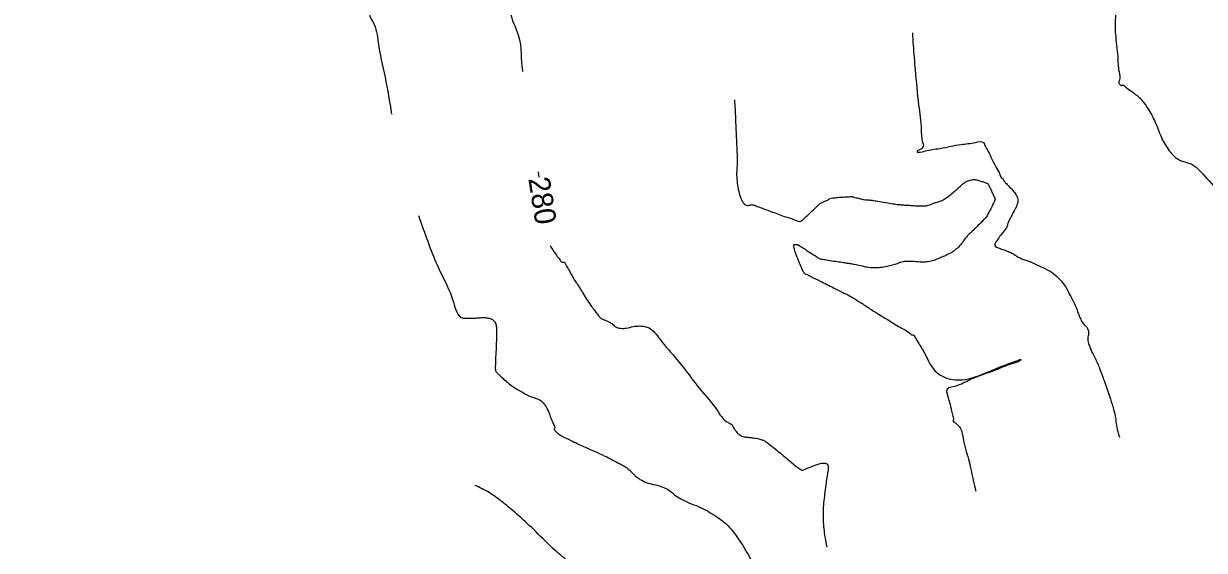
# Model space of a CAD drawing. Extents: x -478102 to -473059, y -1117705 to -1114104.
# Drawn here: x -476292.3 to -476071.3, y -1115340.6 to -1115242.1 of the extents above; entities that cross this region are included whole.
import ezdxf

# ---------------------------------------------------------------- set-up
doc = ezdxf.new("R2010")
doc.units = 0
for name, color, linetype in [('Vrstevnice_hlavni', 7, 'Continuous'), ('Vrstevnice_popis', 7, 'Continuous'), ('Vrstevnice_vedlejsi', 7, 'Continuous')]:
    doc.layers.add(name, color=color, linetype=linetype)

msp = doc.modelspace()

# ---------------------------------------------------------------- linework, layer by layer
at = {"layer": 'Vrstevnice_hlavni'}
msp.add_line((-476196.015, -1115269.846), (-476195.861, -1115270.85), dxfattribs=at)
for points in [[(-476040.384, -1115118.458), (-476041.47, -1115119.89), (-476042.412, -1115121.448), (-476043.751, -1115123.849), (-476045.488, -1115127.091), (-476046.696, -1115129.513), (-476047.375, -1115131.113), (-476047.526, -1115131.894), (-476048.073, -1115133.254), (-476049.018, -1115135.194), (-476050.36, -1115137.713), (-476052.374, -1115140.598), (-476055.061, -1115143.847), (-476058.422, -1115147.462), (-476060.881, -1115150.366), (-476062.441, -1115152.562), (-476063.1, -1115154.048), (-476064.028, -1115155.224), (-476065.225, -1115156.09), (-476066.691, -1115156.645), (-476068.203, -1115157.501), (-476069.761, -1115158.657), (-476071.364, -1115160.113), (-476073.585, -1115161.644), (-476076.424, -1115163.251), (-476079.881, -1115164.932), (-476082.243, -1115166.084), (-476083.511, -1115166.709), (-476083.684, -1115166.806), (-476083.884, -1115166.906), (-476084.109, -1115167.009), (-476084.361, -1115167.115), (-476085.47, -1115168.111), (-476087.436, -1115169.998), (-476090.259, -1115172.776), (-476094.056, -1115175.649), (-476098.828, -1115178.618), (-476104.575, -1115181.683), (-476109.757, -1115183.949), (-476114.374, -1115185.417), (-476118.425, -1115186.088), (-476122.042, -1115187.328), (-476125.226, -1115189.137), (-476127.977, -1115191.516), (-476131.019, -1115193.792), (-476134.353, -1115195.963), (-476137.979, -1115198.031), (-476141.984, -1115199.581), (-476146.368, -1115200.612), (-476151.132, -1115201.124), (-476157.864, -1115204.368), (-476166.565, -1115210.343), (-476177.234, -1115219.049), (-476184.652, -1115224.996), (-476188.817, -1115228.184), (-476189.731, -1115228.613), (-476190.168, -1115228.886), (-476190.128, -1115229.002), (-476189.61, -1115228.963), (-476189.269, -1115228.999), (-476189.104, -1115229.11), (-476189.116, -1115229.298), (-476189.143, -1115229.675), (-476189.187, -1115230.241), (-476189.246, -1115230.996), (-476189.162, -1115231.612), (-476188.933, -1115232.089), (-476188.56, -1115232.427), (-476188.448, -1115232.74), (-476188.595, -1115233.026), (-476189.004, -1115233.287), (-476189.464, -1115233.625), (-476189.976, -1115234.04), (-476190.541, -1115234.531), (-476191.953, -1115235.382), (-476194.211, -1115236.59), (-476197.317, -1115238.157), (-476199.41, -1115239.209), (-476200.49, -1115239.748), (-476200.557, -1115239.773), (-476200.072, -1115243.239), (-476199.036, -1115250.148), (-476198.895, -1115251.068)], [(-476193.757, -1115283.639), (-476192.399, -1115285.697), (-476191.876, -1115286.389), (-476191.509, -1115286.744), (-476191.298, -1115286.761), (-476191.153, -1115286.774), (-476191.075, -1115286.783), (-476191.063, -1115286.789), (-476190.853, -1115287.151), (-476190.446, -1115287.871), (-476189.842, -1115288.948), (-476188.923, -1115290.467), (-476187.688, -1115292.429), (-476186.137, -1115294.833), (-476184.891, -1115296.504), (-476183.948, -1115297.443), (-476183.309, -1115297.648), (-476182.68, -1115297.954), (-476182.06, -1115298.362), (-476181.45, -1115298.872), (-476180.595, -1115299.114), (-476179.497, -1115299.088), (-476178.155, -1115298.795), (-476176.997, -1115298.69), (-476176.025, -1115298.773), (-476175.238, -1115299.045), (-476173.224, -1115301.122), (-476169.984, -1115305.003), (-476165.518, -1115310.689), (-476162.449, -1115314.535), (-476160.779, -1115316.54), (-476160.507, -1115316.704), (-476160.264, -1115316.845), (-476160.048, -1115316.962), (-476159.86, -1115317.056), (-476159.707, -1115317.19), (-476159.59, -1115317.365), (-476159.508, -1115317.58), (-476159.311, -1115317.896), (-476158.998, -1115318.315), (-476158.57, -1115318.834), (-476158.007, -1115319.207), (-476157.308, -1115319.433), (-476156.473, -1115319.513), (-476155.76, -1115319.601), (-476155.169, -1115319.698), (-476154.699, -1115319.804), (-476154.303, -1115319.906), (-476153.978, -1115320.004), (-476153.727, -1115320.098), (-476153.145, -1115320.495), (-476152.232, -1115321.193), (-476150.988, -1115322.193), (-476149.831, -1115323.145), (-476148.761, -1115324.046), (-476147.778, -1115324.899), (-476147.017, -1115325.426), (-476146.478, -1115325.629), (-476146.16, -1115325.507), (-476145.635, -1115325.303), (-476144.904, -1115325.017), (-476143.967, -1115324.649), (-476143.233, -1115324.414), (-476142.702, -1115324.312), (-476142.375, -1115324.342), (-476142.123, -1115324.398), (-476141.945, -1115324.481), (-476141.842, -1115324.59), (-476141.767, -1115324.715), (-476141.722, -1115324.858), (-476141.705, -1115325.018), (-476141.842, -1115326.221), (-476142.131, -1115328.466), (-476142.574, -1115331.753), (-476142.636, -1115334.999), (-476142.32, -1115338.203), (-476141.962, -1115339.984)]]:
    msp.add_spline(points, degree=3, dxfattribs=at)
at = {"layer": 'Vrstevnice_vedlejsi'}
for points in [[(-476075.436, -1115157.873), (-476077.562, -1115158.907), (-476079.639, -1115159.964), (-476081.666, -1115161.045), (-476083.644, -1115162.149), (-476085.921, -1115163.289), (-476088.498, -1115164.465), (-476091.373, -1115165.676), (-476093.656, -1115166.843), (-476095.346, -1115167.967), (-476096.444, -1115169.047), (-476097.921, -1115170.165), (-476099.777, -1115171.319), (-476102.012, -1115172.511), (-476105.743, -1115173.677), (-476110.97, -1115174.816), (-476117.692, -1115175.928), (-476122.561, -1115177.005), (-476125.576, -1115178.045), (-476126.738, -1115179.05), (-476129.738, -1115180.989), (-476134.578, -1115183.864), (-476141.257, -1115187.673), (-476147.035, -1115190.356), (-476151.912, -1115191.911), (-476155.888, -1115192.338), (-476158.789, -1115192.754), (-476160.614, -1115193.159), (-476161.364, -1115193.552), (-476162.517, -1115193.939), (-476164.073, -1115194.319), (-476166.032, -1115194.693), (-476167.609, -1115195.158), (-476168.804, -1115195.715), (-476169.616, -1115196.364), (-476170.816, -1115197.116), (-476172.405, -1115197.973), (-476174.383, -1115198.934), (-476179.537, -1115202.555), (-476187.868, -1115208.836), (-476199.377, -1115217.776), (-476207.75, -1115223.932), (-476212.989, -1115227.302), (-476215.093, -1115227.888), (-476217.31, -1115229.046), (-476219.639, -1115230.776), (-476222.081, -1115233.079), (-476224.102, -1115235.091), (-476225.704, -1115236.812), (-476226.884, -1115238.243), (-476227.475, -1115239.561), (-476227.475, -1115240.767), (-476226.885, -1115241.861), (-476225.939, -1115245.662), (-476224.639, -1115252.17), (-476223.41, -1115259.087)], [(-476290.943, -1115168.232), (-476292.036, -1115168.129), (-476293.289, -1115168.17), (-476294.704, -1115168.355), (-476296.28, -1115168.684), (-476298.044, -1115169.506), (-476299.998, -1115170.82), (-476302.142, -1115172.626), (-476303.749, -1115173.838), (-476304.822, -1115174.454), (-476305.36, -1115174.476), (-476306.141, -1115174.653), (-476307.165, -1115174.987), (-476308.432, -1115175.476), (-476310.431, -1115176.469), (-476313.163, -1115177.965), (-476316.627, -1115179.965), (-476319.342, -1115180.948), (-476321.309, -1115180.916), (-476322.528, -1115179.868), (-476324.355, -1115178.896), (-476326.789, -1115178.002), (-476329.831, -1115177.184), (-476332.146, -1115176.734), (-476333.735, -1115176.651), (-476334.597, -1115176.934), (-476335.575, -1115177.335), (-476336.67, -1115177.853), (-476337.881, -1115178.489), (-476340.138, -1115179.828), (-476343.441, -1115181.87), (-476347.791, -1115184.616), (-476351.193, -1115186.546), (-476353.648, -1115187.661), (-476355.156, -1115187.959), (-476356.569, -1115188.49), (-476357.888, -1115189.253), (-476359.112, -1115190.247), (-476360.257, -1115191.198), (-476361.323, -1115192.106), (-476362.309, -1115192.972), (-476363.814, -1115193.968), (-476365.837, -1115195.095), (-476368.378, -1115196.353), (-476371.783, -1115197.918), (-476376.05, -1115199.79), (-476381.181, -1115201.968), (-476385.269, -1115204.296), (-476388.314, -1115206.773), (-476390.316, -1115209.399), (-476391.767, -1115211.232), (-476392.667, -1115212.272), (-476393.014, -1115212.519), (-476394.789, -1115214.333), (-476397.991, -1115217.713), (-476402.619, -1115222.659), (-476406.002, -1115226.323), (-476408.139, -1115228.705), (-476409.031, -1115229.805), (-476409.796, -1115230.781), (-476410.434, -1115231.632), (-476410.944, -1115232.36), (-476411.453, -1115232.976), (-476411.961, -1115233.481), (-476412.467, -1115233.874), (-476413.193, -1115235.547), (-476414.139, -1115238.502), (-476415.303, -1115242.737), (-476416.343, -1115247.381), (-476417.259, -1115252.434), (-476418.049, -1115257.897), (-476418.052, -1115258.256)], [(-476083.589, -1115227.899), (-476083.618, -1115228.156), (-476083.747, -1115228.632), (-476083.919, -1115228.675), (-476084.163, -1115228.958), (-476084.479, -1115229.481), (-476084.868, -1115230.243), (-476085.18, -1115230.932), (-476085.415, -1115231.547), (-476085.574, -1115232.089), (-476085.972, -1115233.269), (-476086.609, -1115235.087), (-476087.484, -1115237.544), (-476087.928, -1115240.567), (-476087.94, -1115244.158), (-476087.519, -1115248.316), (-476087.274, -1115251.164), (-476087.204, -1115252.702), (-476087.311, -1115252.93), (-476087.328, -1115253.147), (-476087.257, -1115253.355), (-476087.098, -1115253.552), (-476086.936, -1115253.666), (-476086.772, -1115253.697), (-476086.607, -1115253.643), (-476085.981, -1115254.028), (-476084.895, -1115254.851), (-476083.349, -1115256.112), (-476081.88, -1115258.027), (-476080.487, -1115260.597), (-476079.172, -1115263.821), (-476077.645, -1115266.182), (-476075.907, -1115267.682), (-476073.958, -1115268.319), (-476071.269, -1115270.587), (-476067.84, -1115274.487), (-476063.671, -1115280.019), (-476060.648, -1115284.041), (-476058.772, -1115286.555), (-476058.043, -1115287.561), (-476057.529, -1115288.232), (-476057.228, -1115288.568), (-476057.142, -1115288.571), (-476057.059, -1115289.537), (-476056.98, -1115291.466)], [(-476125.929, -1115243.884), (-476125.807, -1115246.158), (-476125.427, -1115250.782), (-476124.774, -1115257.383), (-476124.301, -1115261.931), (-476124.008, -1115264.426), (-476123.894, -1115264.868), (-476123.981, -1115265.246), (-476124.269, -1115265.56), (-476124.757, -1115265.811), (-476125.029, -1115265.996), (-476125.083, -1115266.115), (-476124.92, -1115266.169), (-476123.491, -1115265.956), (-476120.797, -1115265.476), (-476116.836, -1115264.728), (-476114.123, -1115264.363), (-476112.657, -1115264.382), (-476112.438, -1115264.783), (-476111.966, -1115265.692), (-476111.241, -1115267.111), (-476110.263, -1115269.038), (-476109.58, -1115270.343), (-476109.193, -1115271.027), (-476109.102, -1115271.089), (-476109.038, -1115271.136), (-476109.003, -1115271.169), (-476108.995, -1115271.186), (-476108.962, -1115271.248), (-476108.904, -1115271.357), (-476108.821, -1115271.512), (-476108.502, -1115271.894), (-476107.946, -1115272.505), (-476107.155, -1115273.343), (-476106.601, -1115274.081), (-476106.285, -1115274.719), (-476106.206, -1115275.258), (-476106.359, -1115275.986), (-476106.744, -1115276.905)], [(-476159.242, -1115256.374), (-476159.054, -1115259.908), (-476158.82, -1115265.295), (-476158.75, -1115268.706), (-476158.845, -1115270.139), (-476158.769, -1115271.604), (-476158.523, -1115273.101), (-476158.106, -1115274.629), (-476157.613, -1115275.635), (-476157.044, -1115276.119), (-476156.398, -1115276.081), (-476155.961, -1115276.055), (-476155.733, -1115276.04), (-476155.713, -1115276.036), (-476155.581, -1115276.081), (-476155.338, -1115276.173), (-476154.983, -1115276.314), (-476153.911, -1115276.714), (-476152.122, -1115277.373), (-476149.617, -1115278.29), (-476147.877, -1115278.87), (-476146.903, -1115279.111), (-476146.694, -1115279.015), (-476146.533, -1115278.92), (-476146.42, -1115278.827), (-476146.354, -1115278.736), (-476146.034, -1115278.42), (-476145.458, -1115277.878), (-476144.627, -1115277.111), (-476144.009, -1115276.53), (-476143.606, -1115276.135), (-476143.416, -1115275.928), (-476143.115, -1115275.721), (-476142.7, -1115275.515), (-476142.174, -1115275.31), (-476141.777, -1115275.132), (-476141.512, -1115274.98), (-476141.376, -1115274.855), (-476140.853, -1115274.744), (-476139.943, -1115274.647), (-476138.645, -1115274.565), (-476137.773, -1115274.512), (-476137.326, -1115274.488), (-476137.304, -1115274.493), (-476137.022, -1115274.564), (-476136.479, -1115274.699), (-476135.676, -1115274.9), (-476135.01, -1115275.037), (-476134.48, -1115275.109), (-476134.087, -1115275.117), (-476133.301, -1115275.213), (-476132.123, -1115275.399), (-476130.553, -1115275.673), (-476129.267, -1115275.873), (-476128.264, -1115275.998), (-476127.545, -1115276.049), (-476126.691, -1115276.105), (-476125.702, -1115276.169), (-476124.578, -1115276.238), (-476123.673, -1115276.222), (-476122.988, -1115276.122), (-476122.522, -1115275.938), (-476121.968, -1115275.735), (-476121.325, -1115275.516), (-476120.594, -1115275.279), (-476119.818, -1115274.872), (-476118.996, -1115274.295), (-476118.13, -1115273.548), (-476117.407, -1115272.922), (-476116.827, -1115272.417), (-476116.391, -1115272.033), (-476115.924, -1115271.733), (-476115.425, -1115271.516), (-476114.896, -1115271.383), (-476114.504, -1115271.301), (-476114.247, -1115271.269), (-476114.127, -1115271.287), (-476113.822, -1115271.374), (-476113.331, -1115271.529), (-476112.656, -1115271.752), (-476112.177, -1115271.921), (-476111.894, -1115272.035), (-476111.807, -1115272.094), (-476111.623, -1115272.416), (-476111.341, -1115273)], [(-476111.341, -1115273), (-476110.962, -1115273.848), (-476110.694, -1115274.441), (-476110.537, -1115274.78), (-476110.491, -1115274.865), (-476110.47, -1115274.959), (-476110.475, -1115275.062), (-476110.506, -1115275.174), (-476110.69, -1115275.573), (-476111.03, -1115276.26), (-476111.524, -1115277.233), (-476111.877, -1115277.912), (-476112.088, -1115278.296), (-476112.158, -1115278.386), (-476112.514, -1115278.752), (-476113.156, -1115279.397), (-476114.085, -1115280.319), (-476114.761, -1115280.979), (-476115.186, -1115281.379), (-476115.36, -1115281.517), (-476115.713, -1115281.919), (-476116.247, -1115282.585), (-476116.962, -1115283.514), (-476117.741, -1115284.291), (-476118.584, -1115284.915), (-476119.493, -1115285.387), (-476120.392, -1115285.812), (-476121.284, -1115286.191), (-476122.167, -1115286.523), (-476123.251, -1115286.707), (-476124.536, -1115286.741), (-476126.022, -1115286.628), (-476127.231, -1115286.643), (-476128.162, -1115286.786), (-476128.816, -1115287.059), (-476129.654, -1115287.316), (-476130.678, -1115287.555), (-476131.887, -1115287.779), (-476133.124, -1115287.833), (-476134.388, -1115287.719), (-476135.68, -1115287.435), (-476136.751, -1115287.215), (-476137.602, -1115287.058), (-476138.232, -1115286.963), (-476139.134, -1115286.827), (-476140.308, -1115286.649), (-476141.754, -1115286.429), (-476142.752, -1115286.26), (-476143.303, -1115286.142), (-476143.406, -1115286.075), (-476143.876, -1115285.775), (-476144.711, -1115285.24), (-476145.912, -1115284.47), (-476146.719, -1115283.95), (-476147.131, -1115283.678), (-476147.149, -1115283.654), (-476147.194, -1115283.626), (-476147.267, -1115283.594), (-476147.366, -1115283.557), (-476147.542, -1115283.533), (-476147.795, -1115283.522), (-476148.124, -1115283.524), (-476148.141, -1115284.035), (-476147.848, -1115285.056), (-476147.243, -1115286.586), (-476146.785, -1115287.691), (-476146.474, -1115288.372), (-476146.31, -1115288.628), (-476146.156, -1115288.817), (-476146.012, -1115288.938), (-476145.878, -1115288.992), (-476144.948, -1115289.442), (-476143.224, -1115290.289), (-476140.705, -1115291.532), (-476138.75, -1115292.524), (-476137.361, -1115293.265), (-476136.537, -1115293.756), (-476135.685, -1115294.285), (-476134.806, -1115294.853), (-476133.899, -1115295.46), (-476132.503, -1115296.342), (-476130.618, -1115297.498), (-476128.243, -1115298.929), (-476126.641, -1115299.885), (-476125.811, -1115300.366), (-476125.755, -1115300.372), (-476125.7, -1115300.405), (-476125.646, -1115300.464), (-476125.594, -1115300.551), (-476124.922, -1115301.679), (-476123.631, -1115303.848), (-476121.721, -1115307.059), (-476118.902, -1115308.612), (-476115.176, -1115308.508), (-476110.541, -1115306.747), (-476107.432, -1115305.567), (-476105.848, -1115304.97)], [(-476218.376, -1115278.038), (-476217.875, -1115279.456), (-476214.425, -1115288.313), (-476211.835, -1115294.229), (-476210.106, -1115297.205), (-476209.237, -1115297.241), (-476208.349, -1115297.236), (-476207.441, -1115297.189), (-476206.512, -1115297.099), (-476205.696, -1115297.136), (-476204.991, -1115297.297), (-476204.399, -1115297.584), (-476203.999, -1115298.149), (-476203.792, -1115298.991), (-476203.779, -1115300.111), (-476203.805, -1115301.478), (-476203.871, -1115303.093), (-476203.978, -1115304.956), (-476204.004, -1115306.275), (-476203.949, -1115307.051), (-476203.815, -1115307.284), (-476203.415, -1115307.714), (-476202.75, -1115308.342), (-476201.819, -1115309.168), (-476200.943, -1115309.859), (-476200.122, -1115310.415), (-476199.355, -1115310.837), (-476198.758, -1115311.169), (-476198.331, -1115311.411), (-476198.073, -1115311.564), (-476197.577, -1115311.782), (-476196.841, -1115312.065), (-476195.867, -1115312.414), (-476195.041, -1115313.077), (-476194.362, -1115314.054), (-476193.831, -1115315.346), (-476193.423, -1115316.323), (-476193.136, -1115316.986), (-476192.972, -1115317.333), (-476192.894, -1115317.625), (-476192.903, -1115317.861)], [(-476106.744, -1115276.905), (-476107.361, -1115278.014), (-476107.805, -1115278.877), (-476108.078, -1115279.493), (-476108.177, -1115279.862), (-476108.25, -1115280.122), (-476108.297, -1115280.271), (-476108.317, -1115280.311), (-476108.573, -1115280.647), (-476109.065, -1115281.28), (-476109.793, -1115282.209), (-476110.279, -1115282.913), (-476110.525, -1115283.392), (-476110.528, -1115283.645), (-476110.197, -1115283.923), (-476109.532, -1115284.226), (-476108.532, -1115284.553), (-476107.69, -1115284.894), (-476107.005, -1115285.251), (-476106.478, -1115285.622), (-476105.861, -1115285.956), (-476105.153, -1115286.251), (-476104.354, -1115286.507), (-476103.257, -1115286.96), (-476101.863, -1115287.61), (-476100.172, -1115288.455), (-476098.717, -1115289.598), (-476097.498, -1115291.039), (-476096.516, -1115292.777), (-476095.725, -1115294.323), (-476095.126, -1115295.678), (-476094.718, -1115296.841), (-476094.281, -1115297.767), (-476093.815, -1115298.456), (-476093.319, -1115298.907), (-476093.04, -1115299.473), (-476092.976, -1115300.153), (-476093.128, -1115300.947), (-476092.975, -1115301.971), (-476092.517, -1115303.223), (-476091.755, -1115304.704), (-476090.913, -1115306.661), (-476089.99, -1115309.094), (-476088.988, -1115312.004), (-476088.293, -1115314.278), (-476087.906, -1115315.919), (-476087.826, -1115316.925), (-476087.506, -1115318.414), (-476087.193, -1115319.54)], [(-476105.848, -1115304.97), (-476105.79, -1115304.953), (-476105.742, -1115304.95), (-476105.706, -1115304.96), (-476105.681, -1115304.983), (-476105.665, -1115305.007), (-476105.66, -1115305.032), (-476105.665, -1115305.057), (-476105.684, -1115305.087), (-476105.717, -1115305.122), (-476105.765, -1115305.16), (-476107.334, -1115305.771), (-476110.427, -1115306.953), (-476115.042, -1115308.707), (-476118.091, -1115309.993), (-476119.575, -1115310.812), (-476119.492, -1115311.162), (-476119.302, -1115311.898), (-476119.003, -1115313.019), (-476118.597, -1115314.525), (-476118.349, -1115315.58), (-476118.261, -1115316.183), (-476118.333, -1115316.335), (-476118.325, -1115316.469), (-476118.238, -1115316.585), (-476118.073, -1115316.683), (-476117.836, -1115316.872), (-476117.529, -1115317.152), (-476117.151, -1115317.523), (-476116.463, -1115319.666), (-476115.466, -1115323.582), (-476114.16, -1115329.271), (-476114.085, -1115329.578)], [(-476192.903, -1115317.861), (-476192.999, -1115318.042), (-476192.816, -1115318.327), (-476192.354, -1115318.716), (-476191.613, -1115319.21), (-476189.891, -1115320.089), (-476187.188, -1115321.354), (-476183.505, -1115323.005), (-476180.713, -1115324.453), (-476178.814, -1115325.697), (-476177.806, -1115326.737), (-476176.612, -1115327.549), (-476175.23, -1115328.132), (-476173.662, -1115328.486), (-476172.346, -1115328.961), (-476171.282, -1115329.555), (-476170.47, -1115330.27), (-476169.305, -1115330.996), (-476167.786, -1115331.732), (-476165.913, -1115332.48), (-476164.102, -1115333.412), (-476162.353, -1115334.527), (-476160.666, -1115335.826), (-476158.775, -1115338.132), (-476156.681, -1115341.444), (-476154.893, -1115344.811)], [(-476169.317, -1115349.984), (-476170.582, -1115348.511), (-476174.959, -1115344.81), (-476178.893, -1115343.028), (-476182.384, -1115343.164), (-476185.085, -1115343.353), (-476186.997, -1115343.594), (-476188.119, -1115343.887), (-476190.063, -1115342.911), (-476192.828, -1115340.664), (-476196.414, -1115337.147), (-476199.562, -1115334.239), (-476202.271, -1115331.942), (-476204.542, -1115330.254), (-476207.149, -1115328.799), (-476207.747, -1115328.526)]]:
    msp.add_spline(points, degree=3, dxfattribs=at)

# ---------------------------------------------------------------- texts
at = {"layer": 'Vrstevnice_popis'}
msp.add_text(' 280 ', height=4, rotation=279.08544, dxfattribs=at).set_placement((-476198.078, -1115269.663))

doc.saveas('drawing.dxf')
